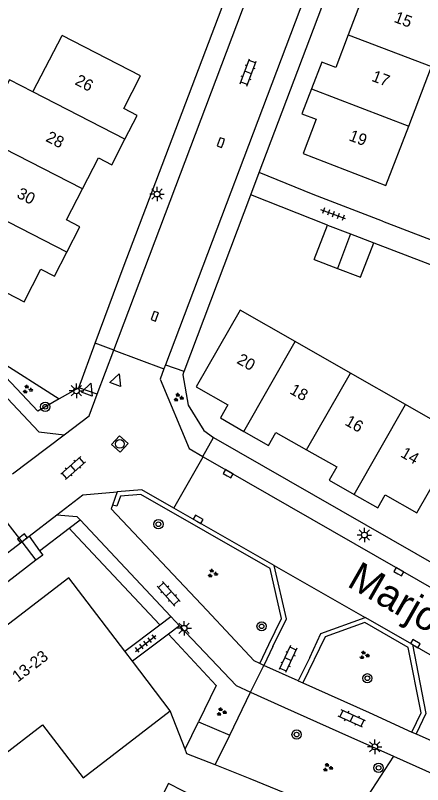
# Model space of a CAD drawing. Extents: x 136000 to 141014, y 402000 to 403500.
# Drawn here: x 137407.6 to 137442.7, y 402050.3 to 402116.6 of the extents above; entities that cross this region are included whole.
import ezdxf

# ---------------------------------------------------------------- set-up
doc = ezdxf.new("R2010")
doc.units = 0
for name, color, linetype in [('gg-afsc-erfafscheiding', 7, 'Continuous'), ('gg-afsc-muur', 7, 'Continuous'), ('gg-anno-huisnummerreeks BGT', 7, 'Continuous'), ('gg-anno-openbare ruimte label', 7, 'Continuous'), ('gg-bbg-bijgebouw', 7, 'Continuous'), ('gg-bbg-gedigitaliseerde bebouwing', 7, 'Continuous'), ('gg-bbg-gedigitaliseerde bijgebouw', 7, 'Continuous'), ('gg-bbg-hoofdgebouw', 7, 'Continuous'), ('gg-bbg-luifel en loopbrug', 7, 'Continuous'), ('gg-bbg-tussenscheiding', 7, 'Continuous'), ('gg-knt-verharding', 7, 'Continuous'), ('gg-knt-verharding nz', 7, 'Continuous'), ('gt-grn-groengrens', 7, 'Continuous'), ('gt-grn-weggrens', 7, 'Continuous'), ('gt-symb-boom', 7, 'Continuous'), ('gt-symb-groenvak', 7, 'Continuous'), ('gt-symb-klinker verharding', 7, 'Continuous'), ('gt-symb-kolk', 7, 'Continuous'), ('gt-symb-lichtmast', 7, 'Continuous'), ('gt-symb-rioolschacht', 7, 'Continuous'), ('gt-symb-tegel verharding', 7, 'Continuous'), ('gt-symb-waterafsluiter', 7, 'Continuous')]:
    doc.layers.add(name, color=color, linetype=linetype)

# ---------------------------------------------------------------- blocks, each defined once
blk = doc.blocks.new('gt0-TEG1')
at = {"layer": 'gt-symb-tegel verharding'}
for p, q in [((-1.125, 0), (1.125, 0)), ((-0.9, -0.25), (-0.9, 0.25)), ((-0.45, -0.25), (-0.45, 0.25)), ((0, -0.25), (0, 0.25)), ((0.45, -0.25), (0.45, 0.25)), ((0.9, -0.25), (0.9, 0.25))]:
    blk.add_line(p, q, dxfattribs=at)
blk = doc.blocks.new('gt0-LMAST')
at = {"layer": 'gt-symb-lichtmast'}
for p, q in [((-0.182, 0.173), (-0.447, 0.438)), ((-0.005, 0.246), (-0.005, 0.621)), ((0.172, 0.173), (0.437, 0.438)), ((-0.255, -0.004), (-0.63, -0.004)), ((-0.182, -0.181), (-0.447, -0.446)), ((-0.005, -0.254), (-0.005, -0.629)), ((0.437, -0.446), (0.172, -0.181)), ((0.245, -0.004), (0.62, -0.004))]:
    blk.add_line(p, q, dxfattribs=at)
blk.add_circle((-0.005, -0.004), 0.25, dxfattribs=at)
blk = doc.blocks.new('gt0-KOLK')
at = {"layer": 'gt-symb-kolk'}
blk.add_lwpolyline([(0, 0), (0.375, 0), (0.375, 0.4), (-0.375, 0.4), (-0.375, 0), (0, 0)], dxfattribs=at)
blk = doc.blocks.new('gt0-BOOM')
at = {"layer": 'gt-symb-boom'}
for radius in [0.4, 0.2]:
    blk.add_circle((0, 0), radius, dxfattribs=at)
blk = doc.blocks.new('gt0-KL1')
at = {"layer": 'gt-symb-klinker verharding'}
for p, q in [((-1.15, 0.3), (1.15, 0.3)), ((-1, -0.3), (-1, 0.3)), ((-0.5, 0.3), (-0.5, 0.45)), ((0, -0.3), (0, 0.3)), ((0.5, 0.3), (0.5, 0.45)), ((1, -0.3), (1, 0.3)), ((-1.15, -0.3), (1.15, -0.3)), ((-0.5, -0.45), (-0.5, -0.3)), ((0.5, -0.45), (0.5, -0.3))]:
    blk.add_line(p, q, dxfattribs=at)
blk = doc.blocks.new('gt0-GRVAK')
at = {"layer": 'gt-symb-groenvak'}
for p, q in [((-0.11, 0.189), (-0.228, 0.24)), ((-0.182, 0.153), (0.088, 0.153)), ((-0.091, 0.211), (-0.156, 0.322)), ((-0.047, 0.214), (-0.047, 0.393)), ((-0.004, 0.211), (0.061, 0.322)), ((0.015, 0.189), (0.133, 0.24)), ((0.262, -0.052), (0.197, 0.059)), ((0.305, -0.049), (0.305, 0.13)), ((0.349, -0.052), (0.414, 0.059)), ((-0.245, -0.228), (-0.363, -0.177)), ((-0.318, -0.264), (-0.047, -0.264)), ((-0.226, -0.206), (-0.291, -0.095)), ((-0.183, -0.203), (-0.183, -0.024)), ((-0.139, -0.206), (-0.074, -0.095)), ((-0.12, -0.228), (-0.002, -0.177)), ((0.243, -0.074), (0.125, -0.023)), ((0.17, -0.11), (0.441, -0.11)), ((0.368, -0.074), (0.486, -0.023))]:
    blk.add_line(p, q, dxfattribs=at)
blk = doc.blocks.new('gt0-WAFSL')
at = {"layer": 'gt-symb-waterafsluiter'}
for p, q in [((-0.5, -0.333), (0, 0.667)), ((0, 0.667), (0.5, -0.333)), ((0.5, -0.333), (-0.5, -0.333))]:
    blk.add_line(p, q, dxfattribs=at)
blk = doc.blocks.new('gt0-RS')
at = {"layer": 'gt-symb-rioolschacht'}
blk.add_lwpolyline([(-0.5, -0.5), (0.5, -0.5), (0.5, 0.5), (-0.5, 0.5)], close=True, dxfattribs=at)
blk.add_circle((0, 0), 0.375, dxfattribs=at)

msp = doc.modelspace()

# ---------------------------------------------------------------- linework, layer by layer
at = {"layer": 'gg-afsc-erfafscheiding'}
for p, q in [((137438.494, 402097.013), (137444.68, 402094.64)), ((137422.22, 402053.361), (137420.946, 402056.662))]:
    msp.add_line(p, q, dxfattribs=at)
for points in [[(137439.243, 402098.872), (137451.464, 402094.191), (137454.39, 402099.34)], [(137422.107, 402085.931), (137422.029, 402085.638), (137422.479, 402083.004), (137423.848, 402080.814), (137424.673, 402080.216)], [(137424.824, 402051.996), (137422.379, 402052.95), (137422.22, 402053.361)], [(137436.595, 402047.22), (137427.826, 402050.806), (137424.824, 402051.996)]]:
    msp.add_lwpolyline(points, dxfattribs=at)
at = {"layer": 'gg-afsc-muur'}
msp.add_line((137439.243, 402098.872), (137433.267, 402101.161), dxfattribs=at)
at = {"layer": 'gg-bbg-bijgebouw'}
for p, q in [((137433.34, 402095.575), (137434.491, 402098.539)), ((137434.491, 402098.539), (137436.497, 402097.774)), ((137436.497, 402097.774), (137438.494, 402097.013))]:
    msp.add_line(p, q, dxfattribs=at)
at = {"layer": 'gg-bbg-gedigitaliseerde bebouwing'}
for p, q in [((137409.096, 402110.013), (137411.616, 402114.885)), ((137441.5, 402107.074), (137443.457, 402112.191)), ((137431.72, 402088.498), (137426.97, 402091.21)), ((137436.478, 402085.781), (137431.72, 402088.498)), ((137441.237, 402083.064), (137436.478, 402085.781))]:
    msp.add_line(p, q, dxfattribs=at)
for points in [[(137409.096, 402110.013), (137407.087, 402111.047), (137404.58, 402106.177), (137406.587, 402105.144)], [(137432.39, 402104.69), (137439.54, 402101.95), (137441.5, 402107.074)], [(137442.21, 402073.72), (137445.99, 402080.35), (137441.237, 402083.064)], [(137404.214, 402050.537), (137406.52, 402052.3), (137406.25, 402052.65), (137409.941, 402055.464), (137413.432, 402050.884)]]:
    msp.add_lwpolyline(points, dxfattribs=at)
at = {"layer": 'gg-bbg-gedigitaliseerde bijgebouw'}
msp.add_line((137433.34, 402095.575), (137435.365, 402094.799), dxfattribs=at)
msp.add_lwpolyline([(137435.365, 402094.799), (137437.354, 402094.037), (137438.494, 402097.013)], dxfattribs=at)
at = {"layer": 'gg-bbg-hoofdgebouw'}
for p, q in [((137418.39, 402111.39), (137411.616, 402114.885)), ((137417.684, 402060.942), (137417.02, 402061.811)), ((137420.946, 402056.662), (137417.684, 402060.942)), ((137413.432, 402050.884), (137420.946, 402056.662))]:
    msp.add_line(p, q, dxfattribs=at)
for points in [[(137437.027, 402120.509), (137436.14, 402118.19), (137437.35, 402117.72), (137436.289, 402114.926)], [(137436.289, 402114.926), (137435.22, 402112.11), (137434, 402112.58), (137433.121, 402110.269)], [(137417.033, 402105.928), (137418.09, 402107.98), (137416.94, 402108.59), (137418.39, 402111.39)], [(137433.121, 402110.269), (137432.3, 402108.11), (137433.51, 402107.65), (137432.39, 402104.69)], [(137413.373, 402101.651), (137414.75, 402104.33), (137415.9, 402103.73), (137417.033, 402105.928)], [(137412.022, 402096.185), (137413.15, 402098.38), (137412, 402098.98), (137413.373, 402101.651)], [(137401.57, 402095.41), (137408.36, 402091.91), (137409.8, 402094.72), (137410.96, 402094.12), (137412.022, 402096.185)], [(137426.97, 402091.21), (137423.18, 402084.6), (137425.92, 402083.03), (137425.28, 402081.91), (137427.293, 402080.753)], [(137427.293, 402080.753), (137429.42, 402079.53), (137430.06, 402080.66), (137432.695, 402079.162)], [(137432.695, 402079.162), (137435.3, 402077.68), (137434.65, 402076.55), (137436.808, 402075.316)], [(137436.808, 402075.316), (137438.83, 402074.16), (137439.47, 402075.29), (137442.21, 402073.72)], [(137417.02, 402061.811), (137412.19, 402068.13), (137400.76, 402059.36), (137404.81, 402054.11), (137402.72, 402052.52), (137404.214, 402050.537)]]:
    msp.add_lwpolyline(points, dxfattribs=at)
at = {"layer": 'gg-bbg-luifel en loopbrug'}
msp.add_lwpolyline([(137423.259, 402049.137), (137420.797, 402050.387), (137417.42, 402043.732), (137419.882, 402042.483)], dxfattribs=at)
at = {"layer": 'gg-bbg-tussenscheiding'}
for p, q in [((137436.289, 402114.926), (137443.457, 402112.191)), ((137433.121, 402110.269), (137441.5, 402107.074)), ((137417.033, 402105.928), (137409.096, 402110.013)), ((137413.373, 402101.651), (137406.587, 402105.144)), ((137412.022, 402096.185), (137404.077, 402100.274)), ((137436.497, 402097.774), (137435.365, 402094.799)), ((137427.293, 402080.753), (137431.72, 402088.498)), ((137432.695, 402079.162), (137436.478, 402085.781)), ((137436.808, 402075.316), (137441.237, 402083.064))]:
    msp.add_line(p, q, dxfattribs=at)
at = {"layer": 'gg-knt-verharding'}
for p, q in [((137428.613, 402103.056), (137439.398, 402131.61)), ((137427.885, 402101.129), (137428.613, 402103.056)), ((137433.267, 402101.161), (137428.613, 402103.056)), ((137434.491, 402098.539), (137427.885, 402101.129)), ((137413.05, 402084.51), (137414.477, 402088.367)), ((137414.652, 402083.949), (137416.09, 402087.757)), ((137416.09, 402087.757), (137420.396, 402086.129)), ((137405.222, 402087.453), (137411.358, 402083.544)), ((137420.526, 402086.472), (137420.396, 402086.129)), ((137420.526, 402086.472), (137422.107, 402085.931)), ((137413.05, 402084.51), (137411.358, 402083.544)), ((137414.652, 402083.949), (137413.05, 402084.51)), ((137407.35, 402077.1), (137411.79, 402080.45)), ((137423.746, 402078.591), (137424.673, 402080.216)), ((137424.673, 402080.216), (137459.328, 402060.347)), ((137421.257, 402074.142), (137423.794, 402078.563)), ((137404.973, 402075.285), (137408.137, 402071.235)), ((137416.37, 402075.53), (137415.962, 402074.393)), ((137429.904, 402069.193), (137421.257, 402074.142)), ((137408.78, 402071.726), (137411.17, 402073.55)), ((137412.223, 402072.397), (137413.179, 402073.123)), ((137413.179, 402073.123), (137420.987, 402064.786)), ((137409.679, 402070.464), (137412.223, 402072.397)), ((137408.137, 402071.235), (137408.78, 402071.726)), ((137408.78, 402071.726), (137409.679, 402070.464)), ((137409.356, 402069.639), (137394.483, 402058.28)), ((137420.033, 402064.071), (137420.987, 402064.786)), ((137420.987, 402064.786), (137421.749, 402063.99)), ((137441.823, 402062.369), (137437.75, 402064.703)), ((137417.02, 402061.811), (137420.033, 402064.071)), ((137421.749, 402063.99), (137420.798, 402063.277)), ((137420.798, 402063.277), (137417.684, 402060.942)), ((137429.792, 402062.197), (137429.017, 402060.575)), ((137432.977, 402061.255), (137431.975, 402059.252)), ((137429.017, 402060.575), (137428.653, 402060.742)), ((137431.975, 402059.252), (137432.379, 402059.071)), ((137427.867, 402058.279), (137430.805, 402056.952)), ((137441.768, 402054.832), (137442.132, 402054.665)), ((137440.19, 402052.759), (137436.595, 402047.22))]:
    msp.add_line(p, q, dxfattribs=at)
for points in [[(137414.477, 402088.367), (137416.88, 402094.86), (137431.917, 402134.438)], [(137422.107, 402085.931), (137422.14, 402085.92), (137427.885, 402101.129)], [(137390.635, 402100.864), (137409.6, 402080.7), (137411.79, 402080.45)], [(137420.396, 402086.129), (137420.06, 402085.24), (137422.58, 402079.26), (137423.746, 402078.591)], [(137411.79, 402080.45), (137413.95, 402082.09), (137414.652, 402083.949)], [(137421.257, 402074.142), (137418.5, 402075.72), (137416.37, 402075.53)], [(137411.17, 402073.55), (137413.419, 402075.267), (137416.37, 402075.53)], [(137415.962, 402074.393), (137415.85, 402074.08), (137424.085, 402065.351)], [(137411.17, 402073.55), (137412.9, 402073.42), (137413.179, 402073.123)], [(137409.679, 402070.464), (137409.946, 402070.089), (137409.356, 402069.639)], [(137429.792, 402062.197), (137430.971, 402064.577), (137429.904, 402069.193)], [(137428.653, 402060.742), (137428.186, 402060.956), (137424.085, 402065.351)], [(137432.977, 402061.255), (137433.912, 402063.34), (137437.75, 402064.703)], [(137421.749, 402063.99), (137426.628, 402058.838), (137427.867, 402058.279)], [(137441.823, 402062.369), (137442.983, 402056.427), (137442.132, 402054.665)], [(137432.379, 402059.071), (137438.08, 402056.523), (137441.768, 402054.832)], [(137430.805, 402056.952), (137435.473, 402054.845), (137440.19, 402052.759)]]:
    msp.add_lwpolyline(points, dxfattribs=at)
at = {"layer": 'gg-knt-verharding nz'}
for p, q in [((137416.09, 402087.757), (137433.498, 402133.841)), ((137437.822, 402132.206), (137420.526, 402086.472)), ((137416.09, 402087.757), (137414.477, 402088.367)), ((137423.746, 402078.591), (137423.794, 402078.563)), ((137423.794, 402078.563), (137461.47, 402056.93)), ((137376.55, 402047.12), (137408.137, 402071.235)), ((137408.137, 402071.235), (137409.356, 402069.639)), ((137429.904, 402069.193), (137437.75, 402064.703)), ((137441.823, 402062.369), (137451.345, 402056.923)), ((137431.975, 402059.252), (137429.017, 402060.575)), ((137442.132, 402054.665), (137445.246, 402053.308)), ((137440.19, 402052.759), (137441.018, 402052.384)), ((137441.018, 402052.384), (137444.042, 402051.018))]:
    msp.add_line(p, q, dxfattribs=at)
at = {"layer": 'gt-grn-groengrens'}
for p, q in [((137412.516, 402072.085), (137412.223, 402072.397)), ((137412.516, 402072.085), (137420.033, 402064.071)), ((137426.074, 402054.576), (137427.867, 402058.279)), ((137422.22, 402053.361), (137423.373, 402055.714)), ((137423.373, 402055.714), (137426.074, 402054.576)), ((137424.824, 402051.996), (137426.074, 402054.576))]:
    msp.add_line(p, q, dxfattribs=at)
for points in [[(137411.358, 402083.544), (137409.53, 402082.5), (137391.473, 402101.632), (137390.635, 402100.864)], [(137428.653, 402060.742), (137429.434, 402062.375), (137430.549, 402064.626), (137429.554, 402068.933), (137418.41, 402075.31), (137416.66, 402075.154), (137416.351, 402074.291), (137415.962, 402074.393)], [(137441.768, 402054.832), (137442.565, 402056.481), (137441.465, 402062.113), (137437.711, 402064.265), (137434.302, 402063.041), (137432.379, 402059.071)], [(137420.798, 402063.277), (137424.906, 402058.843), (137423.373, 402055.714)]]:
    msp.add_lwpolyline(points, dxfattribs=at)
at = {"layer": 'gt-grn-weggrens'}
msp.add_line((137427.867, 402058.279), (137429.017, 402060.575), dxfattribs=at)

# ---------------------------------------------------------------- block references
at = {"layer": 'gt-symb-boom'}
for p in [(137410.168, 402082.872), (137419.922, 402072.747), (137428.822, 402063.945), (137437.937, 402059.464), (137431.838, 402054.616), (137438.907, 402051.747)]:
    msp.add_blockref('gt0-BOOM', p, dxfattribs=at)
at = {"layer": 'gt-symb-groenvak'}
for p in [(137408.631, 402084.369), (137421.64, 402083.671), (137424.58, 402068.506), (137437.665, 402061.45), (137425.343, 402056.566), (137434.515, 402051.768)]:
    msp.add_blockref('gt0-GRVAK', p, dxfattribs=at)
at = {"layer": 'gt-symb-klinker verharding'}
for p, rotation in [((137427.663, 402111.689), 69.33669709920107), ((137412.569, 402077.585), 41.514619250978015), ((137420.808, 402066.746), 131.7144789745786), ((137431.095, 402061.129), -114.64309521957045), ((137436.593, 402056.004), 155.35690477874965)]:
    msp.add_blockref('gt0-KL1', p, dxfattribs=dict(at, rotation=rotation))
at = {"layer": 'gt-symb-kolk'}
for p, rotation in [((137425.502, 402105.575), 69.33669709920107), ((137419.793, 402090.605), 69.33669709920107), ((137425.838, 402076.927), -29.666715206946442), ((137423.249, 402072.998), -29.66671520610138), ((137408.319, 402071.375), 37.36253068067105), ((137440.553, 402068.484), -29.666715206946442), ((137441.977, 402062.285), -29.666715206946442)]:
    msp.add_blockref('gt0-KOLK', p, dxfattribs=dict(at, rotation=rotation))
at = {"layer": 'gt-symb-lichtmast'}
for p in [(137419.807, 402101.211), (137412.86, 402084.254), (137437.683, 402071.818), (137422.142, 402063.782), (137438.579, 402053.563)]:
    msp.add_blockref('gt0-LMAST', p, dxfattribs=at)
at = {"layer": 'gt-symb-rioolschacht', "rotation": 48.00000872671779}
msp.add_blockref('gt0-RS', (137416.596, 402079.664), dxfattribs=at)
at = {"layer": 'gt-symb-tegel verharding'}
for p, rotation in [((137434.997, 402099.464), 160.06095208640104), ((137418.824, 402062.471), 37.729269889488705)]:
    msp.add_blockref('gt0-TEG1', p, dxfattribs=dict(at, rotation=rotation))
at = {"layer": 'gt-symb-waterafsluiter'}
for p, rotation in [((137416.306, 402085.098), -20.30124998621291), ((137413.868, 402084.272), -20.301249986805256)]:
    msp.add_blockref('gt0-WAFSL', p, dxfattribs=dict(at, rotation=rotation))

# ---------------------------------------------------------------- texts
at = {"layer": 'gg-anno-huisnummerreeks BGT'}
for s, rotation, p in [('15', 339.2, (137440.168, 402116.061)), ('17', 339.2, (137438.239, 402110.979)), ('26', 332.6, (137412.65, 402110.696)), ('28', 332.8, (137410.138, 402105.807)), ('19', 339.3, (137436.277, 402105.855)), ('30', 332.8, (137407.638, 402100.943)), ('20', 330.2, (137426.609, 402086.669)), ('18', 330.4, (137431.164, 402084.058)), ('16', 330.4, (137435.926, 402081.35)), ('14', 330.2, (137440.728, 402078.603)), ('13-23', 37.5, (137407.798, 402059.086))]:
    msp.add_text(s, height=1, rotation=rotation, dxfattribs=at).set_placement(p)
at = {"layer": 'gg-anno-openbare ruimte label'}
msp.add_text('Marjolein', height=2.5, rotation=330.2, dxfattribs=at).set_placement((137436.087, 402067.451))

doc.saveas('drawing.dxf')
